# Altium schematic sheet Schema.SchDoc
size A4
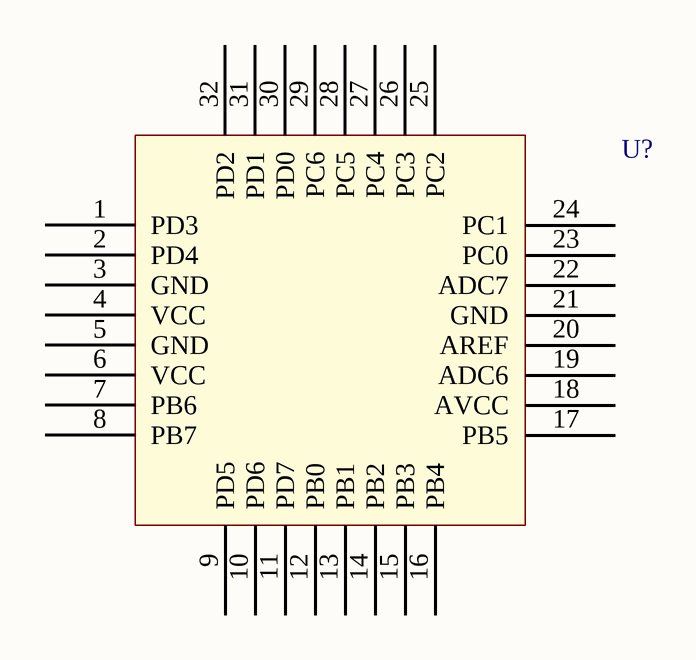
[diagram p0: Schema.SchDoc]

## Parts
U?  ATMEGA328P-MU  [QFN50P500X500X100_HS-33N]  (value not drawn)

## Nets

Not connected (* = marked no-connect by the designer): U? 1(PD3) 2(PD4) 3(GND) 4(VCC) 5(GND) 6(VCC) 7(PB6) 8(PB7) 9(PD5) 10(PD6) 11(PD7) 12(PB0) 13(PB1) 14(PB2) 15(PB3) 16(PB4) 17(PB5) 18(AVCC) 19(ADC6) 20(AREF) 21(GND) 22(ADC7) 23(PC0) 24(PC1) 25(PC2) 26(PC3) 27(PC4) 28(PC5) 29(PC6) 30(PD0) 31(PD1) 32(PD2)

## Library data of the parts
U? = ATMEGA328P-MU: MICROCHIP - ATMEGA328P-MU - MCU 8BIT, AVR, 32K FLASH, 32QFN; Interface: I2C,SPI,UART,USART; Peripherals: Brown-out Detect/Reset,POR,PWM,WDT; Frequency: 20MHz; Number of I/Os: 23; Memory Size: 32KB; Oscillator Type: Internal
